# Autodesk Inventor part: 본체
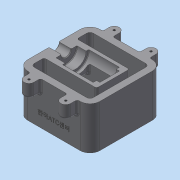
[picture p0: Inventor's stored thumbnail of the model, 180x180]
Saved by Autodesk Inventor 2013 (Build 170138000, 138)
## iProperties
Created: 2018-01
Part Number: 본체
Material: 일반
Document SubType Name: Modeling
Designer: Administrator
Density: 1 g/cm^3
Mass: 368.619 g
Surface Area: 834.392 cm^2
Volume: 368.619 cm^3
Author: Administrator
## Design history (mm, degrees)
sketch "스케치2"
  geometry: L1 (40, 55)-(-40, 55); L2 (-55, 40)-(-55, -40); L3 (-40, -55)-(40, -55); L4 (55, -40)-(55, 40); L5 (55, 55)-(-55, -55); L6 (-55, 55)-(55, -55); A1 r 15 centre (40, -40) between (40, -55) and (55, -40); A2 r 15 centre (40, 40) between (55, 40) and (40, 55); A3 r 15 centre (-40, 40) between (-40, 55) and (-55, 40); A4 r 15 centre (-40, -40) between (-55, -40) and (-40, -55); 1 further point
  constraints: 12 end point, 8 point on circle, 8 point on line, 8 tangent, 4 centre point, 3 equal radius, 2 midpoint, 2 parallel, 1 horizontal, 1 perpendicular
  dimensions: "d0" = 110 distance of L6.end L5.end; "d1" = 110 distance of L5.end L6.start; "d2" = 15 radius of A1
extrude "돌출1" new body sketch "스케치2" distance "d3" = 65; taper "d4" = 0 deg
sketch "스케치3"
  geometry: L1 (-55, 40)-(-55, -40) reference; L2 (-40, -55)-(40, -55) reference; L3 (55, -40)-(55, 40) reference; L4 (40, 55)-(-40, 55) reference; L5 (-35.5, 55)-(-35.5, 65); L6 (-20.5, 55)-(-20.5, 65); L7 (0, 55)-(0, 0); L8 (-35.5, 55)-(-20.5, 55); L9 (35.5, 55)-(20.5, 55); L10 (20.5, 55)-(20.5, 65); L11 (35.5, 55)-(35.5, 65); L12 (-55, 0)-(55, 0); L13 (-20.5, -55)-(-20.5, -65); L14 (-35.5, -55)-(-35.5, -65); L15 (0, -55)-(0, 0); L16 (-35.5, -55)-(-20.5, -55); L17 (40, -55)-(-40, -55); L18 (35.5, -55)-(20.5, -55); L19 (20.5, -55)-(20.5, -65); L20 (35.5, -55)-(35.5, -65); L21 (-40, 55)-(40, 55); A1 r 15 centre (-40, 40) between (-40, 55) and (-55, 40) reference; A2 r 7.5 centre (-28, 65) between (-20.5, 65) and (-35.5, 65); A3 r 7.5 centre (28, 65) between (35.5, 65) and (20.5, 65); A4 r 7.5 centre (-28, -65) between (-35.5, -65) and (-20.5, -65); A5 r 7.5 centre (28, -65) between (20.5, -65) and (35.5, -65); A6 r 15 centre (-40, -40) between (-55, -40) and (-40, -55)
  constraints: 34 end point, 21 symmetric about line, 10 point on circle, 5 centre point, 4 point on line, 3 midpoint, 3 parallel, 2 perpendicular, 2 tangent, 1 collinear, 1 horizontal alignment, 4 other
  dimensions: "d5" = 7.5 radius of A2; "d7" = 28 horizontal distance of L7.end A2.centre; "d8" = 10 distance from line of A2.centre L4
extrude "돌출2" join sketch "스케치3" distance "d9" = 20; taper "d10" = 0 deg
sketch "스케치4"
  geometry: L1 (-55, 40)-(-55, -40) reference; L2 (-40, -55)-(40, -55) reference; L3 (55, -40)-(55, 40) reference; L4 (40, 55)-(-40, 55) reference; L5 (-40, 45)-(40, 45); L6 (45, 40)-(45, -40); L7 (40, -45)-(-40, -45); L8 (-45, -40)-(-45, 40); L9 (-45, 45)-(45, -45); L10 (45, 45)-(-45, -45); A1 r 5 centre (-40, 40) between (-40, 45) and (-45, 40); A2 r 5 centre (40, 40) between (45, 40) and (40, 45); A3 r 5 centre (40, 40) between (45, 40) and (40, 45); A4 r 5 centre (40, -40) between (40, -45) and (45, -40); A5 r 5 centre (-40, -40) between (-45, -40) and (-40, -45); 1 further point
  constraints: 12 end point, 10 point on circle, 10 point on line, 10 tangent, 5 centre point, 2 midpoint, 2 parallel, 1 concentric, 1 horizontal, 1 perpendicular
  dimensions: "d13" = 5 radius of A1; "d14" = 5 radius of A2; "d15" = 5 radius of A4; "d16" = 5 radius of A5; "d17" = 10 distance between parallel lines of L4 L5; "d18" = 10 distance between parallel lines of L3 L6; "d19" = 10 distance between parallel lines of L2 L7 (derived); "d20" = 10 distance between parallel lines of L1 L8 (derived)
extrude "돌출3" cut sketch "스케치4" stored distance "d21" = 20; taper "d22" = 0 deg
sketch "스케치5"
  geometry: L1 (35, 0)-(35, -35); L2 (35, -35)-(-45, -56.436); L3 (55, 0)-(55, -65) reference; L4 (-40, 0)-(40, 0) reference; L5 (-45, 0)-(-40, 0) reference; L6 (35, 0)-(-45, 0); L7 (-45, 0)-(-45, -56.436); L8 (40, -65)-(-40, -65) reference; 1 further point
  constraints: 8 end point, 1 perpendicular, 1 point on line, 1 vertical
  dimensions: "d25" = 20 distance between parallel lines of L3 L1; "d26" = 105 deg angle of L7 L2; "d27" = 30 distance from line of L8 L1.end
extrude "돌출4" join sketch "스케치5" stored distance "d28" = 50; taper "d29" = 0 deg
sketch "스케치7"
  geometry: L1 (-45, 0)-(35, 0) reference; L2 (-55, 0)-(-55, -65) reference; L3 (-55, 0)-(30, 0); L4 (30, 0)-(30, -15); L5 (30, -15)-(25, -15); L6 (25, -15)-(25, -20); L7 (25, -20)-(-22, -20); L8 (-22, -20)-(-22, -16); L9 (-22, -16)-(-36, -16); L10 (-36, -16)-(-36, -7.5); L11 (-36, -7.5)-(-55, -7.5); L12 (-55, 0)-(-55, -7.5); 1 further point
  constraints: 20 end point, 5 perpendicular, 3 parallel, 2 point on line, 1 collinear
  dimensions: "d32" = 15 diameter of L11 L3; "d34" = 32 diameter of L9 L3; "d35" = 40 diameter of L7 L3; "d36" = 30 diameter of L5 L3; "d37" = 5 distance of L4.end L5.end; "d38" = 47 distance of L6.end L7.end; "d39" = 14 distance of L8.end L9.end; "d40" = 19 distance of L10.end L11.end
revolve "회전1" sketch "스케치7" stored, may be unused: angle "d41" = 90 deg
fillet "모깎기1" dims "d42" = 1
sketch "스케치8"
  geometry: L1 (-17, 0)-(-17, -25.757); L2 (-17, -25.757)-(-55, -35.939); L3 (-55, -35.939)-(-55, -53.939); L4 (-55, -53.939)-(20, -33.843); L5 (20, -33.843)-(20, 0); L6 (-55, 0)-(-55, -65) reference; L7 (35, -35)-(-45, -56.436) reference; L8 (-17, 0)-(20, 0); L9 (-22, -16)-(-22, 0) reference; L10 (25, -19)-(25, 0) reference; L11 (-21, 0)-(24, 0) reference; 1 further point
  constraints: 12 end point, 4 parallel, 2 collinear, 1 perpendicular, 1 vertical
  dimensions: "d43" = 5 distance between parallel lines of L7 L4; "d44" = 37 distance of L1.start L5.end; "d45" = 75 deg angle of L6 L2 (derived); "d46" = 18 distance of L2.end L3.end; "d47" = 5 distance between parallel lines of L9 L1; "d48" = 5 distance between parallel lines of L10 L5 (derived)
extrude "돌출5" cut sketch "스케치8" stored distance "d49" = 30; taper "d50" = 0 deg
sketch "스케치9"
  geometry: A1 r 7.5 centre (-28, -65) between (-35.5, -65) and (-20.5, -65) reference; A2 r 7.5 centre (28, -65) between (20.5, -65) and (35.5, -65) reference; A3 r 7.5 centre (28, 65) between (35.5, 65) and (20.5, 65) reference; A4 r 7.5 centre (-28, 65) between (-20.5, 65) and (-35.5, 65) reference; 5 further points
  constraints: 4 coincident
hole "구멍1" sketch "스케치9" at (-28, 65), (28, 65), (28, -65), (-28, -65) diameter "d51" = 3.242; stored, may be unused: countersink angle "d55" = 90 deg, drill point angle "d57" = 118 deg; dims "d52" = 9, "d53" = 4, "d54" = 2, "d56" = 11
fillet "모깎기2" dims "d58" = 3
fillet "모깎기3" dims "d59" = 3
fillet "모깎기4" dims "d60" = 3
fillet "모깎기5" dims "d61" = 3
fillet "모깎기6" dims "d62" = 3
fillet "모깎기7" dims "d63" = 3
chamfer "모따기1" distance "d67" = 1; stored, may be unused: second distance "d68" = 2, angle "d69" = 45 deg
node "작업 평면1"
fillet "모깎기12" dims "d78" = 3
fillet "모깎기13" dims "d79" = 3
sketch "스케치10"
  geometry: L1 (-55, 0)-(-55, -65) reference; L2 (40, -65)-(55, -65) reference; 2 further points
  constraints: 1 other
  dimensions: "d73" = 55 horizontal distance of point (0, -45) L1.end; "d74" = 20 vertical distance of L2.end point (0, -45)
feature "엠보싱1" sketch "스케치10" dims "d0" = 110, "d1" = 110, "d2" = 15, "d75" = 0.5, "d76" = 0
node "솔리드1"
